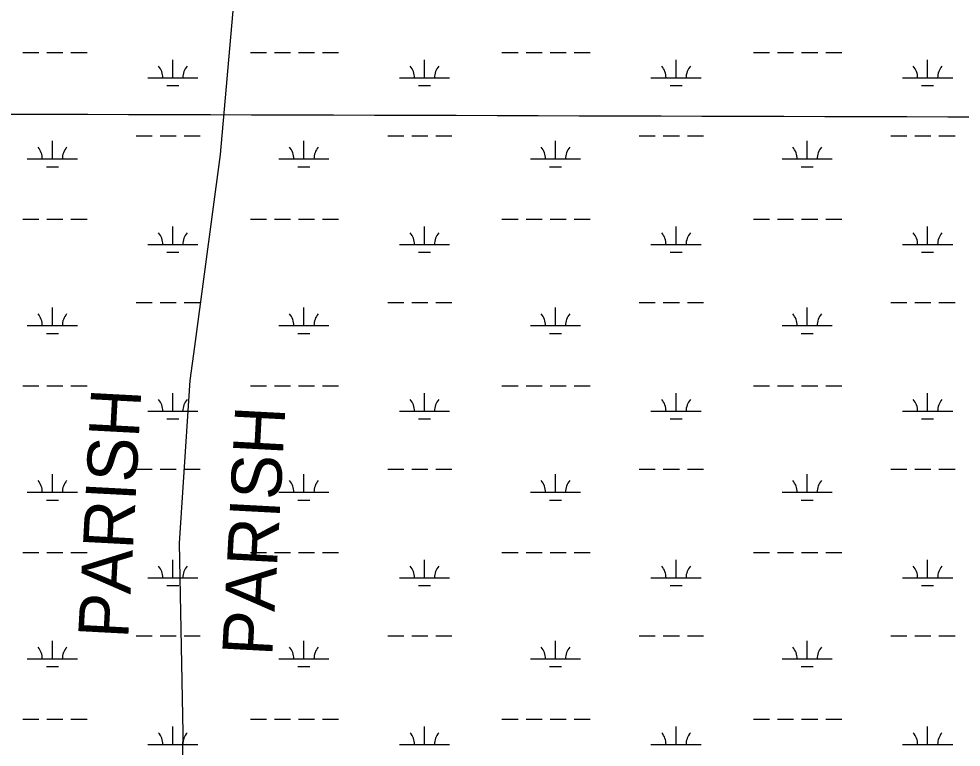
# Model space of a CAD drawing. Extents: x 3161564 to 3199464, y 849354 to 874788.
# Drawn here: x 3177591 to 3179471, y 865645 to 867099 of the extents above; entities that cross this region are included whole.
import ezdxf

# ---------------------------------------------------------------- set-up
doc = ezdxf.new("R2010")
doc.units = 0
for name, color, linetype in [('V-GRID-MAJR', 7, 'Continuous'), ('V-TOPO-BNDY', 7, 'Continuous'), ('V-TOPO-GNAM-IDEN', 7, 'Continuous'), ('V-WETL-SWMP', 7, 'Continuous')]:
    doc.layers.add(name, color=color, linetype=linetype)

msp = doc.modelspace()

# ---------------------------------------------------------------- linework, layer by layer
at = {"layer": 'V-GRID-MAJR'}
msp.add_spline([(3165799.846, 866945.01), (3171028.623, 866928.659), (3176257.404, 866913.068), (3181486.186, 866898.238), (3186714.971, 866884.169), (3191943.758, 866870.86), (3197172.5470000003, 866858.311), (3197172.548, 866858.311)], degree=3, dxfattribs=at)
at = {"layer": 'V-TOPO-BNDY'}
for p, q in [((3177993.256000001, 866828.354999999), (3178019.407000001, 867130.5759999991)), ((3177961.315000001, 866589.9899999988), (3177993.256000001, 866828.354999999)), ((3177941.947000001, 866445.4379999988), (3177961.315000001, 866589.9899999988)), ((3177932.402000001, 866377.3139999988), (3177941.947000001, 866445.4379999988)), ((3177910.842000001, 866052.7059999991), (3177932.402000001, 866377.3139999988)), ((3177918.346000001, 865674.167999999), (3177910.842000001, 866052.7059999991)), ((3177912.368000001, 865293.8599999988), (3177918.346000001, 865674.167999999))]:
    msp.add_line(p, q, dxfattribs=at)
at = {"layer": 'V-WETL-SWMP'}
for p, q in [((3177598.632362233, 867032.1931230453), (3177630.632334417, 867032.1931230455)), ((3177646.6323205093, 867032.1931230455), (3177678.6322926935, 867032.1931230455)), ((3177694.6322787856, 867032.1931230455), (3177726.6322509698, 867032.1931230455)), ((3178052.539967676, 867032.1931230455), (3178084.5399398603, 867032.1931230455)), ((3178100.5399259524, 867032.1931230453), (3178132.5398981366, 867032.1931230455)), ((3178148.5398842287, 867032.1931230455), (3178180.539856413, 867032.1931230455)), ((3178196.539842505, 867032.1931230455), (3178228.539814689, 867032.1931230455)), ((3178554.4475313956, 867032.1931230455), (3178586.44750358, 867032.1931230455)), ((3178602.447489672, 867032.1931230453), (3178634.447461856, 867032.1931230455)), ((3178650.447447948, 867032.1931230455), (3178682.4474201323, 867032.1931230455)), ((3178698.4474062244, 867032.1931230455), (3178730.4473784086, 867032.1931230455)), ((3179056.3550951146, 867032.1931230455), (3179088.3550672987, 867032.1931230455)), ((3179104.355053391, 867032.1931230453), (3179136.355025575, 867032.1931230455)), ((3179152.355011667, 867032.1931230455), (3179184.3549838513, 867032.1931230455)), ((3179200.3549699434, 867032.1931230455), (3179232.3549421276, 867032.1931230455)), ((3177897.9481256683, 866981.4511262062), (3177897.948108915, 867017.4511239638)), ((3178399.8556893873, 866981.4511262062), (3178399.855672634, 867017.4511239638)), ((3178901.7632531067, 866981.4511262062), (3178901.7632363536, 867017.4511239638)), ((3179403.6708168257, 866981.4511262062), (3179403.6708000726, 867017.4511239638)), ((3177847.9481691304, 866981.4511262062), (3177947.9480822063, 866981.4511262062)), ((3178349.85573285, 866981.4511262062), (3178449.8556459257, 866981.4511262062)), ((3178851.7632965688, 866981.4511262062), (3178951.7632096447, 866981.4511262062)), ((3179353.670860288, 866981.4511262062), (3179453.670773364, 866981.4511262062)), ((3177885.94814328, 866966.0201271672), (3177909.9481224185, 866966.0201271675)), ((3178387.855707, 866966.0201271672), (3178411.8556861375, 866966.0201271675)), ((3178889.7632707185, 866966.0201271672), (3178913.763249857, 866966.0201271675)), ((3179391.6708344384, 866966.0201271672), (3179415.670813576, 866966.0201271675)), ((3177824.5402431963, 866866.019133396), (3177856.540215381, 866866.019133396)), ((3177872.540201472, 866866.0191333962), (3177904.5401736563, 866866.019133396)), ((3177920.5401597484, 866866.0191333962), (3177952.5401319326, 866866.019133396)), ((3178326.4478069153, 866866.019133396), (3178358.4477791, 866866.019133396)), ((3178374.4477651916, 866866.0191333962), (3178406.4477373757, 866866.019133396)), ((3178422.447723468, 866866.0191333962), (3178454.447695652, 866866.019133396)), ((3178828.3553706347, 866866.019133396), (3178860.3553428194, 866866.019133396)), ((3178876.355328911, 866866.0191333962), (3178908.355301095, 866866.019133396)), ((3178924.3552871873, 866866.0191333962), (3178956.3552593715, 866866.019133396)), ((3179330.2629343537, 866866.019133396), (3179362.2629065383, 866866.019133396)), ((3179378.26289263, 866866.0191333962), (3179410.262864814, 866866.019133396)), ((3179426.2628509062, 866866.0191333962), (3179458.2628230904, 866866.019133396)), ((3177657.476410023, 866819.5891362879), (3177657.4763932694, 866855.5891340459)), ((3178159.383973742, 866819.5891362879), (3178159.383956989, 866855.5891340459)), ((3178661.2915374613, 866819.5891362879), (3178661.2915207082, 866855.5891340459)), ((3179163.199101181, 866819.5891362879), (3179163.199084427, 866855.5891340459)), ((3177607.476453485, 866819.5891362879), (3177707.4763665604, 866819.5891362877)), ((3177645.4764276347, 866804.1581372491), (3177669.4764067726, 866804.1581372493)), ((3178109.3840172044, 866819.5891362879), (3178209.38393028, 866819.5891362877)), ((3178147.383991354, 866804.1581372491), (3178171.383970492, 866804.1581372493)), ((3178611.291580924, 866819.5891362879), (3178711.291493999, 866819.5891362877)), ((3178649.291555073, 866804.1581372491), (3178673.291534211, 866804.1581372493)), ((3179113.199144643, 866819.5891362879), (3179213.1990577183, 866819.5891362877)), ((3179151.1991187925, 866804.1581372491), (3179175.1990979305, 866804.1581372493)), ((3177598.63251705, 866699.5181437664), (3177630.632489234, 866699.5181437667)), ((3177646.6324753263, 866699.5181437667), (3177678.6324475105, 866699.5181437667)), ((3177694.6324336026, 866699.5181437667), (3177726.632405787, 866699.5181437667)), ((3178052.5401224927, 866699.5181437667), (3178084.540094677, 866699.5181437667)), ((3178100.540080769, 866699.5181437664), (3178132.540052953, 866699.5181437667)), ((3178148.5400390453, 866699.5181437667), (3178180.5400112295, 866699.5181437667)), ((3178196.5399973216, 866699.5181437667), (3178228.5399695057, 866699.5181437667)), ((3178554.447686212, 866699.5181437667), (3178586.4476583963, 866699.5181437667)), ((3178602.4476444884, 866699.5181437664), (3178634.4476166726, 866699.5181437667)), ((3178650.4476027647, 866699.5181437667), (3178682.447574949, 866699.5181437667)), ((3178698.447561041, 866699.5181437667), (3178730.447533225, 866699.5181437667)), ((3179056.3552499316, 866699.5181437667), (3179088.3552221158, 866699.5181437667)), ((3179104.355208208, 866699.5181437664), (3179136.355180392, 866699.5181437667)), ((3179152.355166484, 866699.5181437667), (3179184.3551386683, 866699.5181437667)), ((3179200.3551247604, 866699.5181437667), (3179232.3550969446, 866699.5181437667)), ((3177897.948280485, 866648.7761469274), (3177897.9482637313, 866684.776144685)), ((3178399.855844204, 866648.7761469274), (3178399.8558274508, 866684.776144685)), ((3178901.7634079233, 866648.7761469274), (3178901.76339117, 866684.776144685)), ((3179403.6709716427, 866648.7761469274), (3179403.670954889, 866684.776144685)), ((3177847.948323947, 866648.7761469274), (3177947.948237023, 866648.7761469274)), ((3178349.8558876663, 866648.7761469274), (3178449.8558007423, 866648.7761469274)), ((3178851.763451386, 866648.7761469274), (3178951.7633644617, 866648.7761469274)), ((3179353.6710151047, 866648.7761469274), (3179453.6709281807, 866648.7761469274)), ((3177885.9482980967, 866633.3451478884), (3177909.948277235, 866633.3451478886)), ((3178387.8558618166, 866633.3451478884), (3178411.855840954, 866633.3451478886)), ((3178889.763425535, 866633.3451478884), (3178913.7634046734, 866633.3451478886)), ((3179391.670989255, 866633.3451478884), (3179415.6709683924, 866633.3451478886)), ((3177657.4765648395, 866486.9141570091), (3177657.4765480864, 866522.9141547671)), ((3177824.540398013, 866533.3441541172), (3177856.5403701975, 866533.3441541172)), ((3177872.540356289, 866533.3441541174), (3177904.5403284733, 866533.3441541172)), ((3177920.5403145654, 866533.3441541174), (3177952.5402867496, 866533.3441541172)), ((3178159.384128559, 866486.9141570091), (3178159.3841118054, 866522.9141547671)), ((3178326.447961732, 866533.3441541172), (3178358.4479339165, 866533.3441541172)), ((3178374.447920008, 866533.3441541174), (3178406.4478921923, 866533.3441541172)), ((3178422.4478782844, 866533.3441541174), (3178454.4478504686, 866533.3441541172)), ((3178661.291692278, 866486.9141570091), (3178661.291675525, 866522.9141547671)), ((3178828.3555254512, 866533.3441541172), (3178860.355497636, 866533.3441541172)), ((3178876.3554837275, 866533.3441541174), (3178908.3554559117, 866533.3441541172)), ((3178924.355442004, 866533.3441541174), (3178956.355414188, 866533.3441541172)), ((3179163.1992559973, 866486.9141570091), (3179163.199239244, 866522.9141547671)), ((3179330.2630891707, 866533.3441541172), (3179362.2630613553, 866533.3441541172)), ((3179378.263047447, 866533.3441541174), (3179410.263019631, 866533.3441541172)), ((3179426.2630057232, 866533.3441541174), (3179458.2629779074, 866533.3441541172)), ((3177607.4766083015, 866486.9141570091), (3177707.476521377, 866486.9141570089)), ((3178109.384172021, 866486.9141570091), (3178209.3840850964, 866486.9141570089)), ((3178611.2917357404, 866486.9141570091), (3178711.291648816, 866486.9141570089)), ((3179113.1992994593, 866486.9141570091), (3179213.199212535, 866486.9141570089)), ((3177645.4765824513, 866471.4831579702), (3177669.476561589, 866471.4831579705)), ((3178147.3841461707, 866471.4831579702), (3178171.3841253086, 866471.4831579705)), ((3178649.29170989, 866471.4831579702), (3178673.291689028, 866471.4831579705)), ((3179151.199273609, 866471.4831579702), (3179175.199252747, 866471.4831579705)), ((3177598.6326718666, 866366.8431644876), (3177630.6326440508, 866366.8431644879)), ((3177646.632630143, 866366.8431644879), (3177678.632602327, 866366.8431644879)), ((3177694.632588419, 866366.8431644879), (3177726.6325606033, 866366.8431644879)), ((3178052.5402773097, 866366.8431644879), (3178084.5402494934, 866366.8431644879)), ((3178100.5402355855, 866366.8431644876), (3178132.5402077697, 866366.8431644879)), ((3178148.540193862, 866366.8431644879), (3178180.540166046, 866366.8431644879)), ((3178196.540152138, 866366.8431644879), (3178228.5401243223, 866366.8431644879)), ((3178554.4478410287, 866366.8431644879), (3178586.447813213, 866366.8431644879)), ((3178602.447799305, 866366.8431644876), (3178634.447771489, 866366.8431644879)), ((3178650.4477575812, 866366.8431644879), (3178682.4477297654, 866366.8431644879)), ((3178698.4477158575, 866366.8431644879), (3178730.4476880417, 866366.8431644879)), ((3179056.355404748, 866366.8431644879), (3179088.3553769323, 866366.8431644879)), ((3179104.3553630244, 866366.8431644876), (3179136.3553352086, 866366.8431644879)), ((3179152.3553213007, 866366.8431644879), (3179184.355293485, 866366.8431644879)), ((3179200.355279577, 866366.8431644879), (3179232.355251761, 866366.8431644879)), ((3177897.9484353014, 866316.1011676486), (3177897.9484185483, 866352.1011654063)), ((3178399.855999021, 866316.1011676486), (3178399.8559822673, 866352.1011654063)), ((3178901.76356274, 866316.1011676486), (3178901.7635459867, 866352.1011654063)), ((3179403.6711264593, 866316.1011676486), (3179403.671109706, 866352.1011654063)), ((3177847.9484787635, 866316.1011676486), (3177947.9483918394, 866316.1011676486)), ((3178349.856042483, 866316.1011676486), (3178449.855955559, 866316.1011676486)), ((3178851.7636062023, 866316.1011676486), (3178951.7635192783, 866316.1011676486)), ((3179353.6711699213, 866316.1011676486), (3179453.671082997, 866316.1011676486)), ((3177885.948452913, 866300.6701686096), (3177909.9484320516, 866300.6701686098)), ((3178387.856016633, 866300.6701686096), (3178411.8559957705, 866300.6701686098)), ((3178889.763580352, 866300.6701686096), (3178913.7635594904, 866300.6701686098)), ((3179391.6711440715, 866300.6701686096), (3179415.671123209, 866300.6701686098)), ((3177657.476719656, 866154.23917773), (3177657.476702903, 866190.239175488)), ((3177824.54055283, 866200.6691748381), (3177856.540525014, 866200.6691748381)), ((3177872.5405111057, 866200.6691748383), (3177904.54048329, 866200.6691748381)), ((3177920.5404693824, 866200.6691748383), (3177952.5404415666, 866200.6691748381)), ((3178159.3842833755, 866154.23917773), (3178159.3842666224, 866190.239175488)), ((3178326.448116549, 866200.6691748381), (3178358.4480887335, 866200.6691748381)), ((3178374.4480748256, 866200.6691748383), (3178406.4480470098, 866200.6691748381)), ((3178422.448033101, 866200.6691748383), (3178454.448005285, 866200.6691748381)), ((3178661.2918470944, 866154.23917773), (3178661.2918303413, 866190.239175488)), ((3178828.3556802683, 866200.6691748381), (3178860.3556524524, 866200.6691748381)), ((3178876.355638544, 866200.6691748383), (3178908.3556107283, 866200.6691748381)), ((3178924.355596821, 866200.6691748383), (3178956.355569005, 866200.6691748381)), ((3179163.199410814, 866154.23917773), (3179163.1993940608, 866190.239175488)), ((3179330.263243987, 866200.6691748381), (3179362.263216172, 866200.6691748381)), ((3179378.263202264, 866200.6691748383), (3179410.263174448, 866200.6691748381)), ((3179426.26316054, 866200.6691748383), (3179458.263132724, 866200.6691748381)), ((3177607.476763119, 866154.23917773), (3177707.476676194, 866154.2391777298)), ((3178109.3843268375, 866154.23917773), (3178209.384239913, 866154.2391777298)), ((3178611.2918905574, 866154.23917773), (3178711.2918036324, 866154.2391777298)), ((3179113.1994542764, 866154.23917773), (3179213.199367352, 866154.2391777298)), ((3177645.4767372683, 866138.8081786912), (3177669.4767164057, 866138.8081786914)), ((3178147.3843009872, 866138.8081786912), (3178171.384280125, 866138.8081786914)), ((3178649.2918647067, 866138.8081786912), (3178673.2918438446, 866138.8081786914)), ((3179151.1994284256, 866138.8081786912), (3179175.1994075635, 866138.8081786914)), ((3177598.632826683, 866034.1681852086), (3177630.6327988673, 866034.1681852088)), ((3177646.63278496, 866034.1681852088), (3177678.632757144, 866034.1681852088)), ((3177694.6327432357, 866034.1681852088), (3177726.63271542, 866034.1681852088)), ((3178052.5404321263, 866034.1681852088), (3178084.5404043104, 866034.1681852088)), ((3178100.540390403, 866034.1681852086), (3178132.540362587, 866034.1681852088)), ((3178148.540348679, 866034.1681852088), (3178180.540320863, 866034.1681852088)), ((3178196.540306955, 866034.1681852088), (3178228.5402791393, 866034.1681852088)), ((3178554.4479958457, 866034.1681852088), (3178586.44796803, 866034.1681852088)), ((3178602.4479541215, 866034.1681852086), (3178634.4479263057, 866034.1681852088)), ((3178650.4479123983, 866034.1681852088), (3178682.4478845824, 866034.1681852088)), ((3178698.447870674, 866034.1681852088), (3178730.4478428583, 866034.1681852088)), ((3179056.3555595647, 866034.1681852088), (3179088.355531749, 866034.1681852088)), ((3179104.3555178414, 866034.1681852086), (3179136.3554900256, 866034.1681852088)), ((3179152.355476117, 866034.1681852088), (3179184.3554483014, 866034.1681852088)), ((3179200.3554343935, 866034.1681852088), (3179232.3554065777, 866034.1681852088)), ((3177897.9485901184, 865983.4261883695), (3177897.9485733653, 866019.4261861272)), ((3178399.8561538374, 865983.4261883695), (3178399.856137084, 866019.4261861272)), ((3178901.763717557, 865983.4261883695), (3178901.7637008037, 866019.4261861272)), ((3179403.671281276, 865983.4261883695), (3179403.6712645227, 866019.4261861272)), ((3177847.9486335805, 865983.4261883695), (3177947.9485466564, 865983.4261883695)), ((3178349.8561973, 865983.4261883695), (3178449.8561103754, 865983.4261883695)), ((3178851.763761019, 865983.4261883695), (3178951.763674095, 865983.4261883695)), ((3179353.6713247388, 865983.4261883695), (3179453.6712378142, 865983.4261883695)), ((3177885.9486077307, 865967.9951893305), (3177909.948586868, 865967.9951893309)), ((3178387.8561714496, 865967.9951893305), (3178411.8561505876, 865967.9951893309)), ((3178889.763735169, 865967.9951893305), (3178913.763714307, 865967.9951893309)), ((3179391.671298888, 865967.9951893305), (3179415.671278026, 865967.9951893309)), ((3177824.5407076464, 865867.9941955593), (3177856.5406798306, 865867.9941955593)), ((3177872.540665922, 865867.9941955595), (3177904.5406381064, 865867.9941955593)), ((3177920.540624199, 865867.9941955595), (3177952.540596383, 865867.9941955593)), ((3178326.4482713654, 865867.9941955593), (3178358.44824355, 865867.9941955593)), ((3178374.448229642, 865867.9941955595), (3178406.4482018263, 865867.9941955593)), ((3178422.448187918, 865867.9941955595), (3178454.448160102, 865867.9941955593)), ((3178828.355835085, 865867.9941955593), (3178860.355807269, 865867.9941955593)), ((3178876.3557933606, 865867.9941955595), (3178908.355765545, 865867.9941955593)), ((3178924.3557516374, 865867.9941955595), (3178956.3557238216, 865867.9941955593)), ((3179330.263398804, 865867.9941955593), (3179362.2633709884, 865867.9941955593)), ((3179378.2633570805, 865867.9941955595), (3179410.2633292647, 865867.9941955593)), ((3179426.2633153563, 865867.9941955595), (3179458.2632875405, 865867.9941955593)), ((3177657.4768744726, 865821.5641984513), (3177657.4768577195, 865857.5641962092)), ((3178159.384438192, 865821.5641984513), (3178159.384421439, 865857.5641962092)), ((3178661.2920019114, 865821.5641984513), (3178661.291985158, 865857.5641962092)), ((3179163.1995656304, 865821.5641984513), (3179163.1995488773, 865857.5641962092)), ((3177607.4769179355, 865821.5641984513), (3177707.4768310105, 865821.5641984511)), ((3178109.384481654, 865821.5641984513), (3178209.3843947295, 865821.5641984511)), ((3178611.292045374, 865821.5641984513), (3178711.291958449, 865821.5641984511)), ((3179113.199609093, 865821.5641984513), (3179213.1995221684, 865821.5641984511)), ((3177645.476892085, 865806.1331994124), (3177669.4768712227, 865806.1331994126)), ((3178147.384455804, 865806.1331994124), (3178171.3844349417, 865806.1331994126)), ((3178649.292019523, 865806.1331994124), (3178673.291998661, 865806.1331994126)), ((3179151.1995832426, 865806.1331994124), (3179175.1995623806, 865806.1331994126)), ((3177598.6329814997, 865701.4932059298), (3177630.632953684, 865701.49320593)), ((3177646.6329397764, 865701.49320593), (3177678.6329119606, 865701.49320593)), ((3177694.632898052, 865701.49320593), (3177726.6328702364, 865701.49320593)), ((3178052.540586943, 865701.49320593), (3178084.540559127, 865701.49320593)), ((3178100.5405452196, 865701.4932059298), (3178132.5405174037, 865701.49320593)), ((3178148.5405034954, 865701.49320593), (3178180.5404756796, 865701.49320593)), ((3178196.5404617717, 865701.49320593), (3178228.540433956, 865701.49320593)), ((3178554.4481506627, 865701.49320593), (3178586.448122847, 865701.49320593)), ((3178602.448108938, 865701.4932059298), (3178634.4480811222, 865701.49320593)), ((3178650.448067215, 865701.49320593), (3178682.448039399, 865701.49320593)), ((3178698.4480254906, 865701.49320593), (3178730.447997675, 865701.49320593)), ((3179056.355714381, 865701.49320593), (3179088.3556865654, 865701.49320593)), ((3179104.355672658, 865701.4932059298), (3179136.355644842, 865701.49320593)), ((3179152.355630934, 865701.49320593), (3179184.355603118, 865701.49320593)), ((3179200.35558921, 865701.49320593), (3179232.3555613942, 865701.49320593)), ((3177897.948744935, 865650.7512090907), (3177897.948728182, 865686.7512068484)), ((3178399.856308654, 865650.7512090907), (3178399.856291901, 865686.7512068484)), ((3178901.763872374, 865650.7512090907), (3178901.7638556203, 865686.7512068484)), ((3179403.6714360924, 865650.7512090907), (3179403.6714193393, 865686.7512068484)), ((3177847.948788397, 865650.7512090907), (3177947.948701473, 865650.7512090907)), ((3178349.8563521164, 865650.7512090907), (3178449.856265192, 865650.7512090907)), ((3178851.7639158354, 865650.7512090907), (3178951.7638289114, 865650.7512090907)), ((3179353.6714795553, 865650.7512090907), (3179453.671392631, 865650.7512090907))]:
    msp.add_line(p, q, dxfattribs=at)
for centre, radius, start, end in [((3177842.705237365, 866981.9259293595), 35.24628790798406, 359.2281793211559, 40.771837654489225), ((3177953.19101353, 866981.9259293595), 35.24628790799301, 139.2281775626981, 180.77183589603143), ((3178344.612801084, 866981.9259293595), 35.24628790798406, 359.2281793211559, 40.771837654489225), ((3178455.09857725, 866981.9259293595), 35.24628790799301, 139.2281775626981, 180.77183589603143), ((3178846.5203648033, 866981.9259293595), 35.24628790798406, 359.2281793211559, 40.771837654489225), ((3178957.0061409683, 866981.9259293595), 35.24628790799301, 139.2281775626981, 180.77183589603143), ((3179348.427928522, 866981.9259293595), 35.24628790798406, 359.2281793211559, 40.771837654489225), ((3179458.913704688, 866981.9259293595), 35.24628790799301, 139.2281775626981, 180.77183589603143), ((3177602.2335217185, 866820.0639394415), 35.24628790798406, 359.2281793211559, 40.771837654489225), ((3177712.7192978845, 866820.0639394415), 35.24628790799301, 139.2281775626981, 180.77183589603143), ((3178104.141085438, 866820.0639394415), 35.24628790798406, 359.2281793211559, 40.771837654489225), ((3178214.626861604, 866820.0639394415), 35.24628790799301, 139.2281775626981, 180.77183589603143), ((3178606.048649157, 866820.0639394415), 35.24628790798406, 359.2281793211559, 40.771837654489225), ((3178716.534425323, 866820.0639394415), 35.24628790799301, 139.2281775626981, 180.77183589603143), ((3179107.9562128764, 866820.0639394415), 35.24628790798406, 359.2281793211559, 40.771837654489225), ((3179218.4419890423, 866820.0639394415), 35.24628790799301, 139.2281775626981, 180.77183589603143), ((3177842.7053921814, 866649.2509500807), 35.24628790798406, 359.2281793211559, 40.771837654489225), ((3177953.1911683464, 866649.2509500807), 35.24628790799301, 139.2281775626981, 180.77183589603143), ((3178344.6129559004, 866649.2509500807), 35.24628790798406, 359.2281793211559, 40.771837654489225), ((3178455.0987320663, 866649.2509500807), 35.24628790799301, 139.2281775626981, 180.77183589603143), ((3178846.52051962, 866649.2509500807), 35.24628790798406, 359.2281793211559, 40.771837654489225), ((3178957.006295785, 866649.2509500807), 35.24628790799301, 139.2281775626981, 180.77183589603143), ((3179348.428083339, 866649.2509500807), 35.24628790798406, 359.2281793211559, 40.771837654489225), ((3179458.9138595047, 866649.2509500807), 35.24628790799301, 139.2281775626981, 180.77183589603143), ((3177602.233676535, 866487.3889601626), 35.24628790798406, 359.2281793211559, 40.771837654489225), ((3177712.719452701, 866487.3889601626), 35.24628790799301, 139.2281775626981, 180.77183589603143), ((3178104.1412402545, 866487.3889601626), 35.24628790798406, 359.2281793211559, 40.771837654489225), ((3178214.6270164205, 866487.3889601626), 35.24628790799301, 139.2281775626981, 180.77183589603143), ((3178606.048803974, 866487.3889601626), 35.24628790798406, 359.2281793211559, 40.771837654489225), ((3178716.53458014, 866487.3889601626), 35.24628790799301, 139.2281775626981, 180.77183589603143), ((3179107.956367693, 866487.3889601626), 35.24628790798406, 359.2281793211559, 40.771837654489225), ((3179218.442143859, 866487.3889601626), 35.24628790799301, 139.2281775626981, 180.77183589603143), ((3177842.705546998, 866316.5759708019), 35.24628790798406, 359.2281793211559, 40.771837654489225), ((3177953.191323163, 866316.5759708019), 35.24628790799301, 139.2281775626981, 180.77183589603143), ((3178344.613110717, 866316.5759708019), 35.24628790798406, 359.2281793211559, 40.771837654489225), ((3178455.098886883, 866316.5759708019), 35.24628790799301, 139.2281775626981, 180.77183589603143), ((3178846.520674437, 866316.5759708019), 35.24628790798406, 359.2281793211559, 40.771837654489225), ((3178957.006450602, 866316.5759708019), 35.24628790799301, 139.2281775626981, 180.77183589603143), ((3179348.4282381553, 866316.5759708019), 35.24628790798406, 359.2281793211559, 40.771837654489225), ((3179458.9140143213, 866316.5759708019), 35.24628790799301, 139.2281775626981, 180.77183589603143), ((3177602.2338313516, 866154.7139808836), 35.24628790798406, 359.2281793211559, 40.771837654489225), ((3177712.7196075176, 866154.7139808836), 35.24628790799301, 139.2281775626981, 180.77183589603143), ((3178104.141395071, 866154.7139808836), 35.24628790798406, 359.2281793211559, 40.771837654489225), ((3178214.627171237, 866154.7139808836), 35.24628790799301, 139.2281775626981, 180.77183589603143), ((3178606.0489587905, 866154.7139808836), 35.24628790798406, 359.2281793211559, 40.771837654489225), ((3178716.5347349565, 866154.7139808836), 35.24628790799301, 139.2281775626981, 180.77183589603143), ((3179107.9565225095, 866154.7139808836), 35.24628790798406, 359.2281793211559, 40.771837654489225), ((3179218.4422986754, 866154.7139808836), 35.24628790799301, 139.2281775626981, 180.77183589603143), ((3177842.7057018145, 865983.9009915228), 35.24628790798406, 359.2281793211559, 40.771837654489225), ((3177953.19147798, 865983.9009915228), 35.24628790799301, 139.2281775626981, 180.77183589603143), ((3178344.613265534, 865983.9009915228), 35.24628790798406, 359.2281793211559, 40.771837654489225), ((3178455.0990416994, 865983.9009915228), 35.24628790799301, 139.2281775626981, 180.77183589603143), ((3178846.5208292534, 865983.9009915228), 35.24628790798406, 359.2281793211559, 40.771837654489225), ((3178957.006605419, 865983.9009915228), 35.24628790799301, 139.2281775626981, 180.77183589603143), ((3179348.4283929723, 865983.9009915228), 35.24628790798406, 359.2281793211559, 40.771837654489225), ((3179458.914169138, 865983.9009915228), 35.24628790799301, 139.2281775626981, 180.77183589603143), ((3177602.2339861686, 865822.0390016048), 35.24628790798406, 359.2281793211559, 40.771837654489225), ((3177712.7197623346, 865822.0390016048), 35.24628790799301, 139.2281775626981, 180.77183589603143), ((3178104.1415498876, 865822.0390016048), 35.24628790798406, 359.2281793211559, 40.771837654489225), ((3178214.6273260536, 865822.0390016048), 35.24628790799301, 139.2281775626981, 180.77183589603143), ((3178606.049113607, 865822.0390016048), 35.24628790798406, 359.2281793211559, 40.771837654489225), ((3178716.534889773, 865822.0390016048), 35.24628790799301, 139.2281775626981, 180.77183589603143), ((3179107.9566773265, 865822.0390016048), 35.24628790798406, 359.2281793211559, 40.771837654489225), ((3179218.4424534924, 865822.0390016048), 35.24628790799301, 139.2281775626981, 180.77183589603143), ((3177842.7058566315, 865651.226012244), 35.24628790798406, 359.2281793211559, 40.771837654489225), ((3177953.191632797, 865651.226012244), 35.24628790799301, 139.2281775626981, 180.77183589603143), ((3178344.6134203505, 865651.226012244), 35.24628790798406, 359.2281793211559, 40.771837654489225), ((3178455.099196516, 865651.226012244), 35.24628790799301, 139.2281775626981, 180.77183589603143), ((3178846.52098407, 865651.226012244), 35.24628790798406, 359.2281793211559, 40.771837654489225), ((3178957.0067602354, 865651.226012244), 35.24628790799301, 139.2281775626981, 180.77183589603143), ((3179348.4285477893, 865651.226012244), 35.24628790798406, 359.2281793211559, 40.771837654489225), ((3179458.914323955, 865651.226012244), 35.24628790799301, 139.2281775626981, 180.77183589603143)]:
    msp.add_arc(centre, radius, start, end, dxfattribs=at)

# ---------------------------------------------------------------- texts
at = {"layer": 'V-TOPO-GNAM-IDEN'}
for p in [(3177808.6398513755, 865860.8533716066), (3178096.004640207, 865826.0039027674)]:
    msp.add_text('PARISH', height=99.99980199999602, rotation=86.95469682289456, dxfattribs=at).set_placement(p)

doc.saveas('drawing.dxf')
